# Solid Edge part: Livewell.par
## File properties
Username: m_hel
Author: m_hel
Template: Iso Metric Part.par
Last saved by: m_hel
Revision: 8
Application: Solid Edge
Accuracy: 0,990
Material: Glass Fiber
Face Style: White (dull)
Fill Style: ANSI36(Marble)
Virtual Style: ANSI36(Marble)
Grouping: Uncategorized
LibraryName: Custom Materials
Coef. of Thermal Exp: 0.0
Thermal Conductivity: 0.0
Specific Heat: 0.0
Modulus of Elasticity: 0.0
Poisson's Ratio: 0.0
Yield Stress: 0.0
Ultimate Stress: 0.0
Elongation: 0.0
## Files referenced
..\..\Redfisher18.asm
G:\OneDriveTemp\OneDrive\Dokumendid\TLÜ tööd\3D Modelleerimine\3d modelling\veesõiduk\Boxes\Livewell.par
G:\OneDriveTemp\OneDrive\Dokumendid\TLÜ tööd\3D Modelleerimine\3d modelling\veesõiduk\Deck1.par
iduk\Boxes\Livewell.par
iduk\Deck1.par
iduk\Redfisher18.asm
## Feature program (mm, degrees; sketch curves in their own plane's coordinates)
sketch for "unnamed Protrusion 1" plane through (0, 0, 0) normal (0, 0, 1) x-axis (1, 0, 0)
  line (-250, -1810) -> (-250, -2140)
  arc centre (-240, -2140) radius 10 from (-250, -2140) to (-240, -2150) ccw
  line (-240, -2150) -> (240, -2150)
  arc centre (240, -2140) radius 10 from (240, -2150) to (250, -2140) ccw
  line (250, -2140) -> (250, -1810)
  arc centre (240, -1810) radius 10 from (250, -1810) to (240, -1800) ccw
  line (240, -1800) -> (-240, -1800)
  arc centre (-240, -1810) radius 10 from (-240, -1800) to (-250, -1810) ccw
extrude "unnamed Protrusion 1" add finite 200 along -normal
thinwall "Thinwall_1"  Thickness = 50 mm
thinwall "Thinwall_2"  Thickness = 20 mm
fillet "Round_1" radius 30
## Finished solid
Body 1: solid body, 44 faces, 96 edges, 56 vertices.
  Faces by surface: cylinder 20, plane 16, blend 4, sphere 4
  Edges by curve: line 56, circle 32, ellipse 8
Bounding box of the edges (mm; curved faces can reach further): 600.000 x 450.000 x 220.000, from (-300, -2200, -220) to (300, -1750, 0).
Cylindrical faces by radius (mm): R10 x4, R30 x12, R60 x4
Spherical faces by radius (mm): R30 x4
Planar faces by outward normal: +x 3, +y 3, +z 2, -x 3, -y 3, -z 2
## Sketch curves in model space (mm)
arc centre (-240, -2140, 0) radius 10 from (-250, -2140, 0) through (-246.8624, -2147.2737, 0) to (-240, -2150, 0)
line (-240, -2150, 0) -> (240, -2150, 0)
arc centre (240, -2140, 0) radius 10 from (240, -2150, 0) through (247.2737, -2146.8624, 0) to (250, -2140, 0)
line (250, -2140, 0) -> (250, -1810, 0)
arc centre (240, -1810, 0) radius 10 from (250, -1810, 0) through (246.8624, -1802.7263, 0) to (240, -1800, 0)
line (240, -1800, 0) -> (-240, -1800, 0)
arc centre (-240, -1810, 0) radius 10 from (-240, -1800, 0) through (-247.2737, -1803.1376, 0) to (-250, -1810, 0)
line (-250, -1810, 0) -> (-250, -2140, 0)
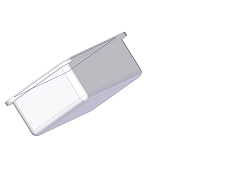
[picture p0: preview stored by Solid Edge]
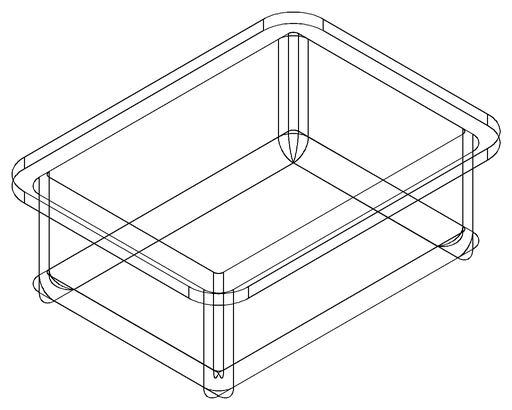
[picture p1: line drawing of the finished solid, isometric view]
